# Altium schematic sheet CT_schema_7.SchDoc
size 479 x 328 mm
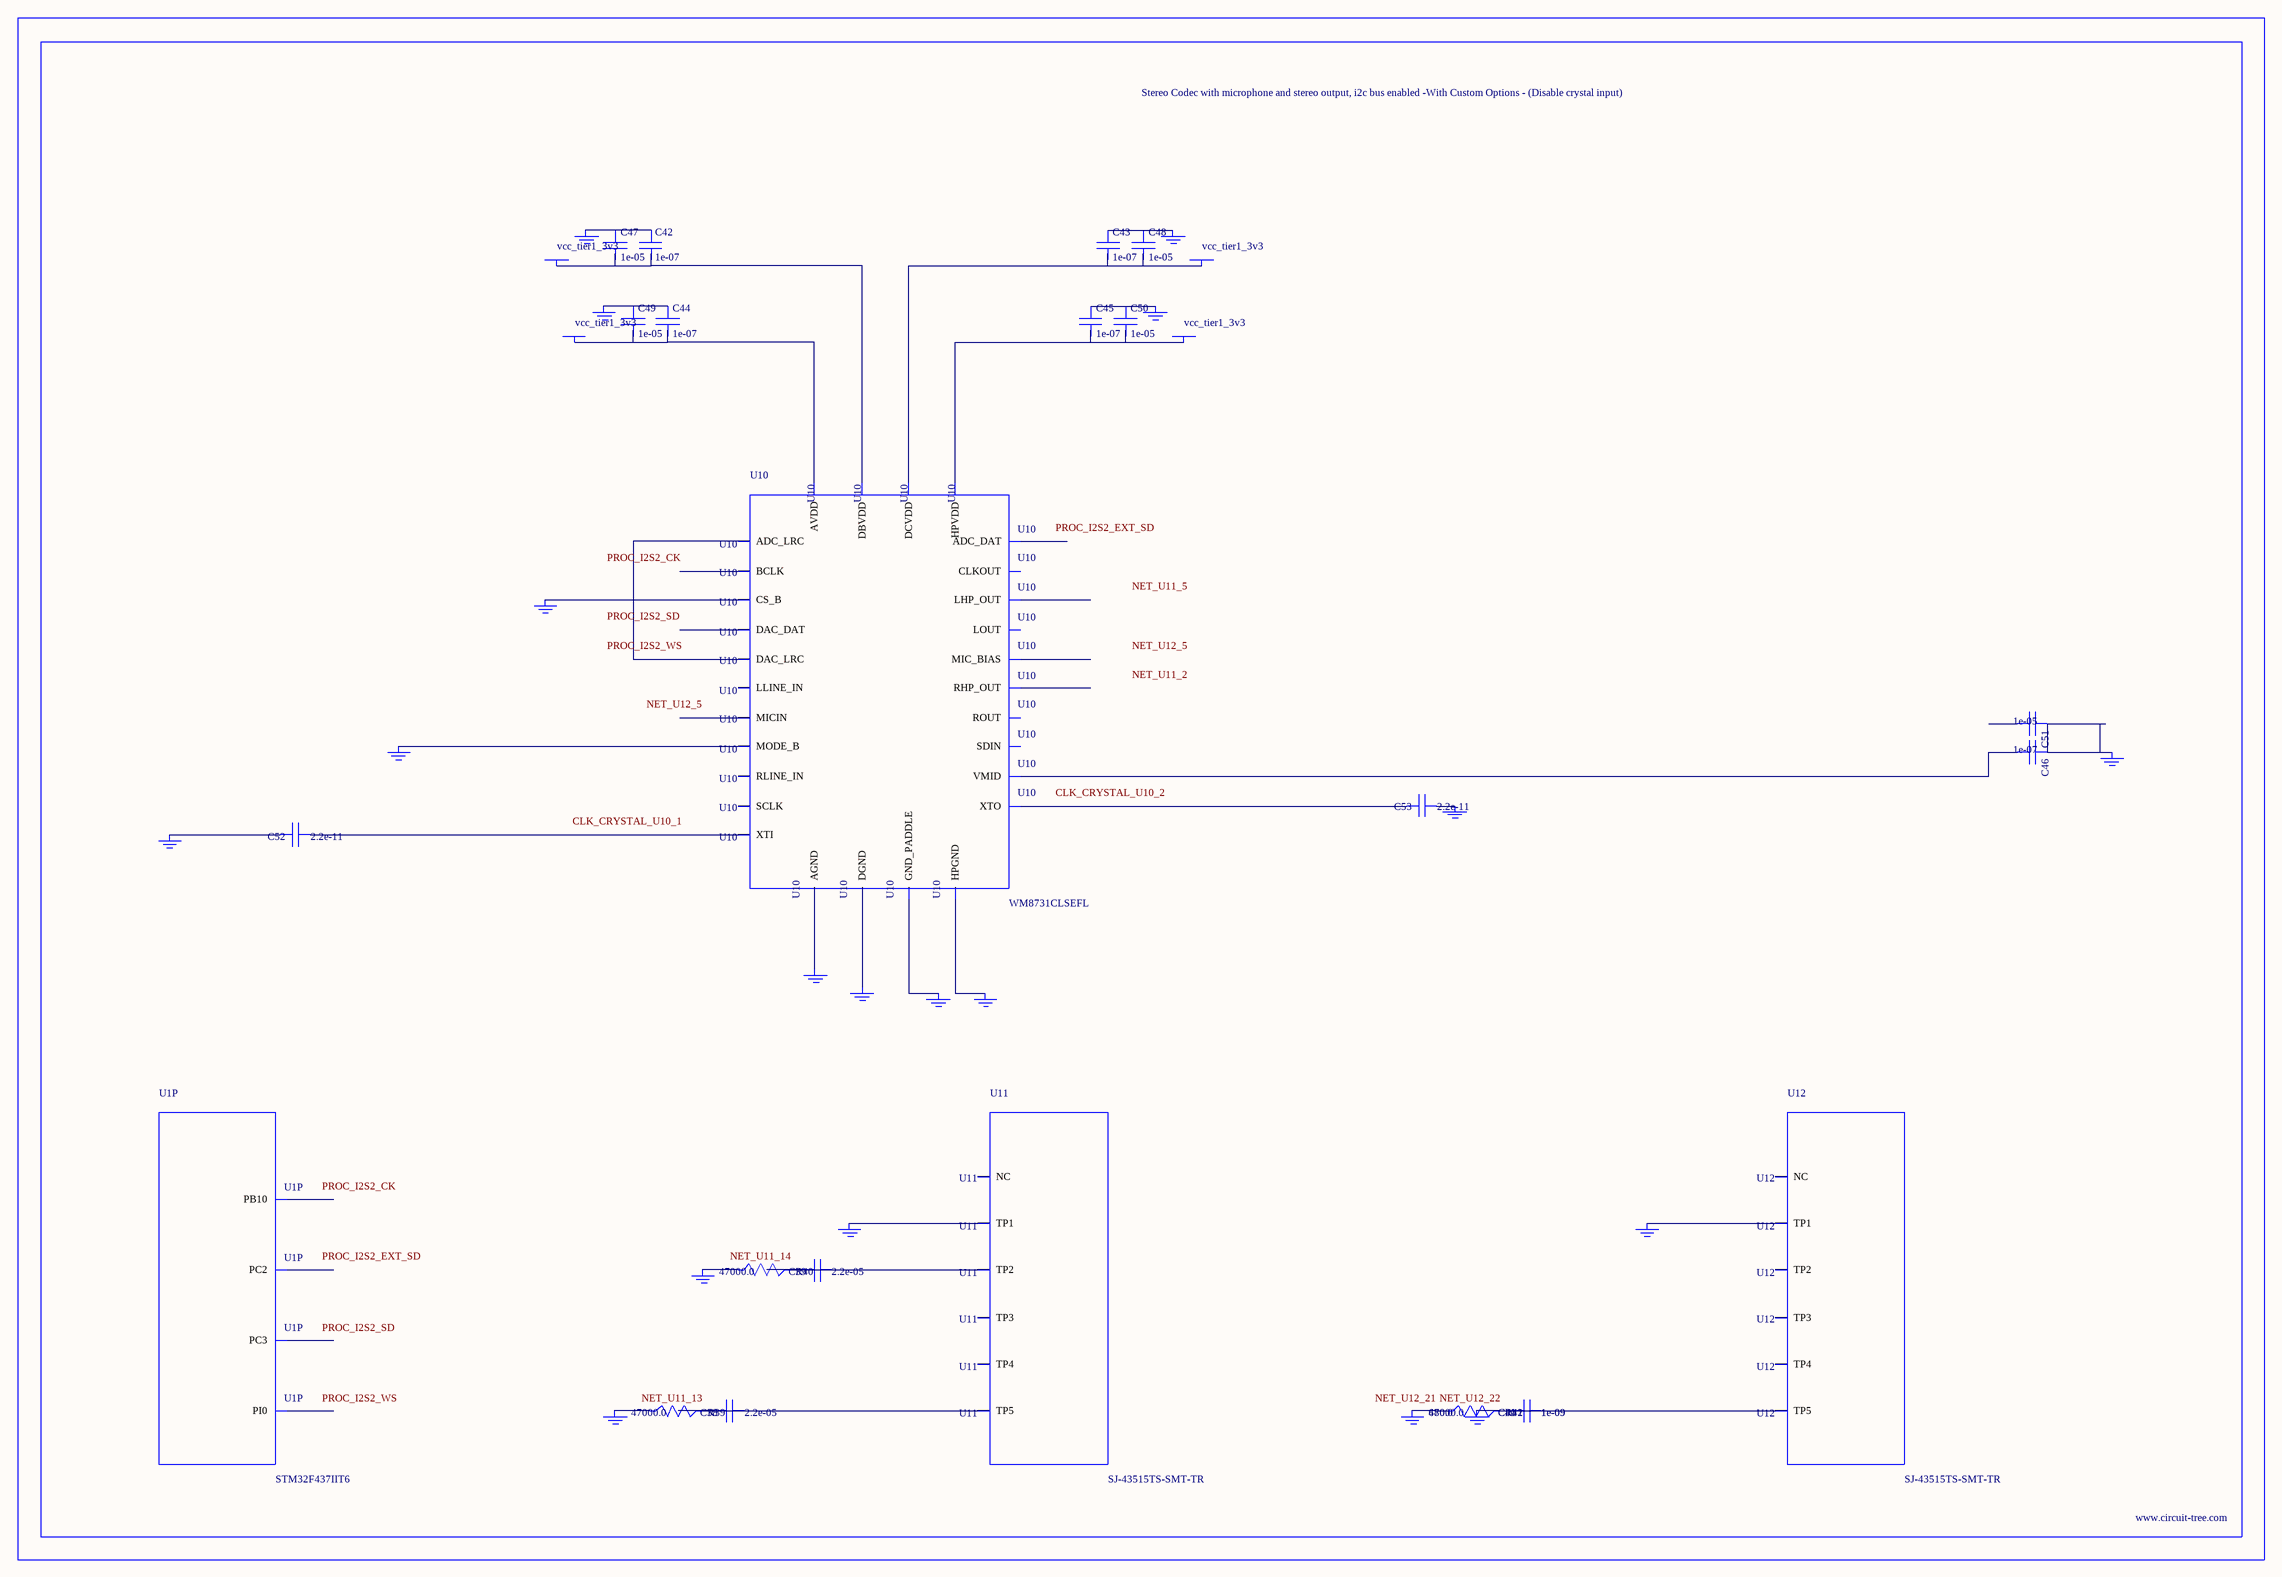
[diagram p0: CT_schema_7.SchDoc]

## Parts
BORDER6  (no value)
C38  2.2e-05  [C1210]
C39  2.2e-05  [C1210]
C40  1e-09  [C0402]
C41  1e-09  [C0402]
C42  1e-07  [C0402]
C43  1e-07  [C0402]
C44  1e-07  [C0402]
C45  1e-07  [C0402]
C46  1e-07  [C0402]
C47  1e-05  [C0805]
C48  1e-05  [C0805]
C49  1e-05  [C0805]
C50  1e-05  [C0805]
C51  1e-05  [C0805]
C52  2.2e-11  [C0402]
C53  2.2e-11  [C0402]
GND_INSTANCE_6_0  (no value)
GND_INSTANCE_6_1  (no value)
GND_INSTANCE_6_2  (no value)
GND_INSTANCE_6_3  (no value)
GND_INSTANCE_6_4  (no value)
GND_INSTANCE_6_5  (no value)
GND_INSTANCE_6_6  (no value)
GND_INSTANCE_6_7  (no value)
GND_INSTANCE_6_8  (no value)
GND_INSTANCE_6_9  (no value)
GND_INSTANCE_6_10  (no value)
GND_INSTANCE_6_11  (no value)
GND_INSTANCE_6_12  (no value)
GND_INSTANCE_6_13  (no value)
GND_INSTANCE_6_14  (no value)
GND_INSTANCE_6_15  (no value)
GND_INSTANCE_6_16  (no value)
GND_INSTANCE_6_17  (no value)
GND_INSTANCE_6_18  (no value)
POWER_INSTANCE_6_0  vcc_tier1_3v3
POWER_INSTANCE_6_1  vcc_tier1_3v3
POWER_INSTANCE_6_2  vcc_tier1_3v3
POWER_INSTANCE_6_3  vcc_tier1_3v3
R39  47000.0  [R0603]
R40  47000.0  [R0603]
R41  47000.0  [R0603]
R42  680.0  [R0603]
U1  STM32F437IIT6  [LQFP176]  (part P of 16)
U10  WM8731CLSEFL  [QFN-28]
U11  SJ-43515TS-SMT-TR  [SJ-43515TS-SMT-TR]
U12  SJ-43515TS-SMT-TR  [SJ-43515TS-SMT-TR]

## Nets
NetC38_1: C38.1 C38.2 R39.2 U11.5(TP5)
NetC39_1: C39.1 C39.2 R40.2 U11.2(TP2)
NetC40_1: C40.1 C40.2 C41.1 C41.2 GND_INSTANCE_6_18.0(GND) R41.2 R42.2 U12.5(TP5)
NetC42_1: C42.1 C47.1 GND_INSTANCE_6_3.0(GND)
NetC42_2: C42.2 C47.2 POWER_INSTANCE_6_1.0(PWR) U10.5(DBVDD)
NetC43_1: C43.1 C48.1 GND_INSTANCE_6_2.0(GND)
NetC43_2: C43.2 C48.2 POWER_INSTANCE_6_0.0(PWR) U10.3(DCVDD)
NetC44_1: C44.1 C49.1 GND_INSTANCE_6_6.0(GND)
NetC44_2: C44.2 C49.2 POWER_INSTANCE_6_3.0(PWR) U10.18(AVDD)
NetC45_1: C45.1 C50.1 GND_INSTANCE_6_4.0(GND)
NetC45_2: C45.2 C50.2 POWER_INSTANCE_6_2.0(PWR) U10.12(HPVDD)
NetC46_1: C46.1 C51.1 GND_INSTANCE_6_7.0(GND)
NetC46_2: C46.2 U10.20(VMID)
NetC52_1: C52.1 U10.1(XTI)
NetC52_2: C52.2 GND_INSTANCE_6_0.0(GND)
NetC53_1: C53.1 GND_INSTANCE_6_1.0(GND)
NetC53_2: C53.2 U10.2(XTO)
NetGND_INSTANCE_6_5_0: GND_INSTANCE_6_5.0(GND) U10.15(HPGND)
NetGND_INSTANCE_6_8_0: GND_INSTANCE_6_8.0(GND) U10.25(MODE_B)
NetGND_INSTANCE_6_9_0: GND_INSTANCE_6_9.0(GND) U10.26(CS_B)
NetGND_INSTANCE_6_10_0: GND_INSTANCE_6_10.0(GND) U10.29(GND_PADDLE)
NetGND_INSTANCE_6_11_0: GND_INSTANCE_6_11.0(GND) U10.4(DGND)
NetGND_INSTANCE_6_12_0: GND_INSTANCE_6_12.0(GND) U10.19(AGND)
NetGND_INSTANCE_6_13_0: GND_INSTANCE_6_13.0(GND) U11.1(TP1)
NetGND_INSTANCE_6_14_0: GND_INSTANCE_6_14.0(GND) R40.1
NetGND_INSTANCE_6_15_0: GND_INSTANCE_6_15.0(GND) R39.1
NetGND_INSTANCE_6_16_0: GND_INSTANCE_6_16.0(GND) U12.1(TP1)
NetGND_INSTANCE_6_17_0: GND_INSTANCE_6_17.0(GND) R41.1 R42.1
NetU10_9: U10.9(DAC_LRC) U10.11(ADC_LRC)

Not connected (* = marked no-connect by the designer): C51 2; U1 34(PC2) 35(PC3) 79(PB10) 131(PI0); U10 6(CLKOUT) 7(BCLK) 8(DAC_DAT) 10(ADC_DAT) 13(LHP_OUT) 14(RHP_OUT) 16(LOUT) 17(ROUT) 21(MIC_BIAS) 22(MICIN) 23(RLINE_IN) 24(LLINE_IN) 27(SDIN) 28(SCLK); U11 3(TP3) 4(TP4) 6(NC); U12 2(TP2) 3(TP3) 4(TP4) 6(NC)

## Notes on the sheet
- Labels drawn without touching a wire or pin: CLK_CRYSTAL_U10_1, CLK_CRYSTAL_U10_2, NET_U11_2, NET_U11_5, NET_U11_13, NET_U11_14, NET_U12_5, NET_U12_21, NET_U12_22, PROC_I2S2_CK, PROC_I2S2_EXT_SD, PROC_I2S2_SD, PROC_I2S2_WS

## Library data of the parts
BORDER6 = BORDER_PAGE6
C38 C39 = C1210C224K5RACTU
C40 C41 = C0402C102K3RAC
C42-C46 = C0402C104K3RACTU
C47-C51 = C0805C106K8RACTU
C52 C53 = C0402C220K3RAC
GND_INSTANCE_6_0-GND_INSTANCE_6_18 = GND
POWER_INSTANCE_6_0-POWER_INSTANCE_6_3 = PWR
R39-R41 = RC0603JR-0747KL
R42 = RC0603JR-07680RL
